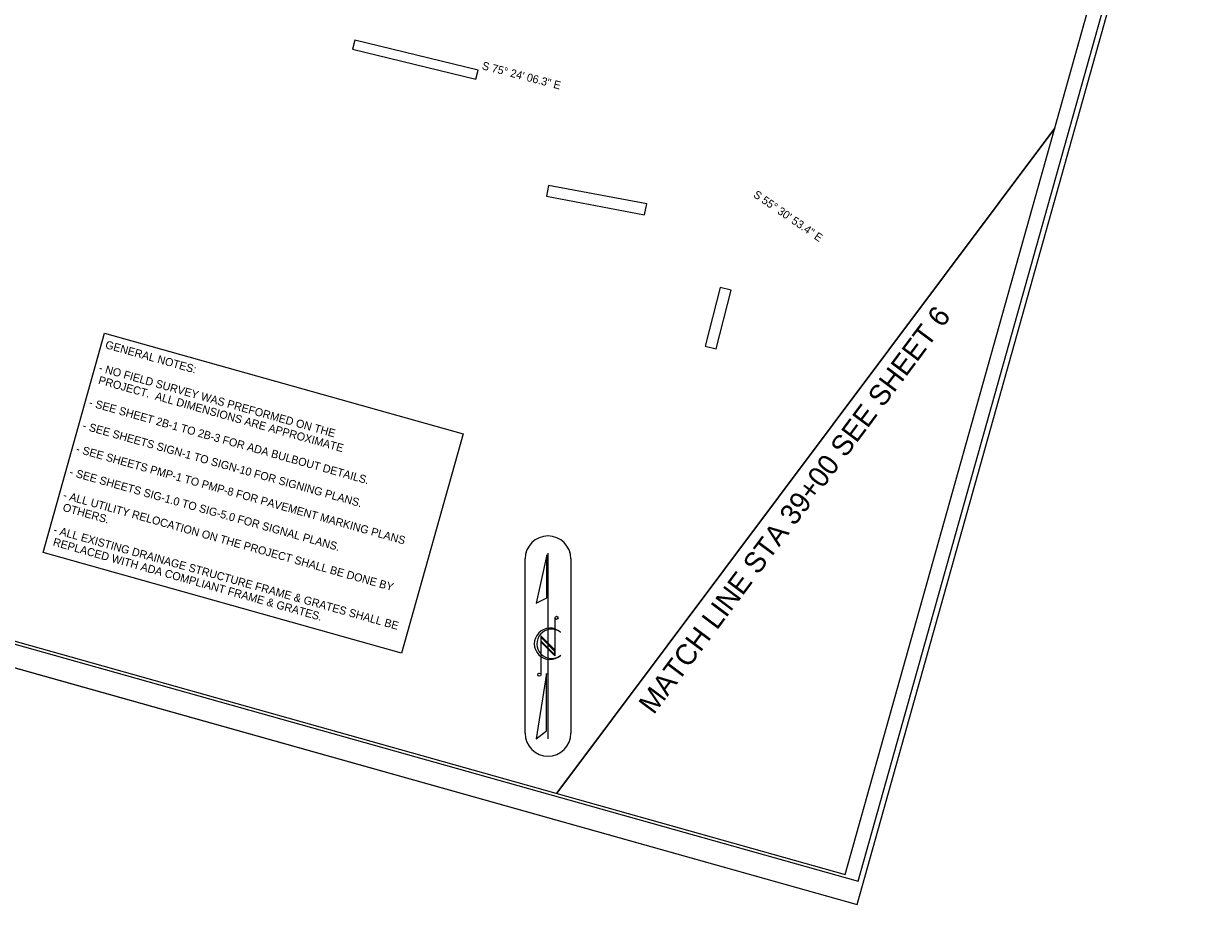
# Model space of a CAD drawing. Extents: x 928111 to 937215, y 684320 to 686530.
# Drawn here: x 929882 to 930907, y 684943 to 685714 of the extents above; entities that cross this region are included whole.
import ezdxf

# ---------------------------------------------------------------- set-up
doc = ezdxf.new("R2010")
doc.units = 0
for name, color, linetype in [('Exist Horizontal Alignment Direction Label', 7, 'Continuous'), ('Exist Horizontal Alignment Station Label', 7, 'Continuous'), ('Matchline', 7, 'Continuous'), ('Matchline Text', 7, 'Continuous'), ('Prop DSN Text', 7, 'Continuous'), ('Sheet Cutting Line CELL', 7, 'Continuous'), ('Sheet Layout Plan Border', 7, 'Continuous'), ('Sheet Plan CELL', 7, 'Continuous'), ('Sheet Plan Layout CELL', 7, 'Continuous'), ('Sheet Plot Border Inside CELL', 7, 'Continuous'), ('Sheet Plot Border Outside CELL', 7, 'Continuous')]:
    doc.layers.add(name, color=color, linetype=linetype)

msp = doc.modelspace()

# ---------------------------------------------------------------- linework, layer by layer
at = {"layer": 'Exist Horizontal Alignment Station Label'}
for p, q in [((930321, 685093.1), (930321, 685245.6)), ((930361, 685245.6), (930361, 685093.1))]:
    msp.add_line(p, q, dxfattribs=at)
for centre, start, end in [((930341, 685245.6), 90, 180), ((930341, 685245.6), 0, 90), ((930341, 685093.1), 180, 270), ((930341, 685093.1), 270, 0)]:
    msp.add_arc(centre, 20, start, end, dxfattribs=at)
at = {"layer": 'Matchline'}
msp.add_line((930784.2, 685621.9), (930348.6, 685040.6), dxfattribs=at)
at = {"layer": 'Prop DSN Text'}
for points in [[(930170.1, 685691.2), (930278, 685664.9), (930279.9, 685672.7), (930172, 685698.9)], [(930339.7, 685562.5), (930425.5, 685546.4), (930427.3, 685555.9), (930341.5, 685572)], [(930491.7, 685482.8), (930478.4, 685431.6), (930488, 685429.1), (930501.3, 685480.3)], [(929953.2, 685442.8), (930266.7, 685354.7), (930212.9, 685163.2), (929899.4, 685251.2)]]:
    msp.add_lwpolyline(points, close=True, dxfattribs=at)
at = {"layer": 'Sheet Cutting Line CELL'}
msp.add_line((928990.5, 685398.6), (930611.3, 684943.4), dxfattribs=at)
at = {"layer": 'Sheet Layout Plan Border'}
for p, q in [((930348.6, 685040.6), (930784.2, 685621.9)), ((930666.4, 685464.7), (930663.4, 685460.7))]:
    msp.add_line(p, q, dxfattribs=at)
at = {"layer": 'Sheet Plan CELL'}
for p, q in [((930341, 685088.1), (930341, 685250.6)), ((930347.1, 685194), (930347.1, 685160.7)), ((930347.1, 685165.9), (930334.7, 685178.3)), ((930334.7, 685178.3), (930334.7, 685144.4)), ((930351.7, 685181.6), (930351.9, 685181.5)), ((930347.1, 685164.6), (930334.7, 685177.1)), ((930334.7, 685177.1), (930334.7, 685174)), ((930347.1, 685161.6), (930334.7, 685174)), ((930334.7, 685174), (930347.1, 685161.6)), ((930347.1, 685160.7), (930334.7, 685173.1)), ((930347.1, 685161.6), (930347.1, 685164.6))]:
    msp.add_line(p, q, dxfattribs=at)
for points in [[(930884.9, 685980.5), (929440.8, 686386.2), (929156.9, 685375.3), (930601, 684969.7)], [(930339.9, 685249.1), (930330.6, 685206.9), (930339.9, 685211.6)], [(930339.7, 685145.3), (930330.5, 685088.1), (930339.7, 685095.3)]]:
    msp.add_lwpolyline(points, close=True, dxfattribs=at)
for centre in [(930348.5, 685194), (930333.4, 685144.3)]:
    msp.add_circle(centre, 1.32, dxfattribs=at)
for centre, radius, start, end in [((930342.7, 685171.3), 13.7, 47.84, 312.3941), ((930344.1, 685171.3), 12.8, 53.095, 308.6287)]:
    msp.add_arc(centre, radius, start, end, dxfattribs=at)
at = {"layer": 'Sheet Plan Layout CELL'}
msp.add_lwpolyline([(929440.8, 686386.2), (929156.9, 685375.3), (930601, 684969.7), (930827.7, 685776.9), (930597.4, 685841.6), (930654.6, 686045.2)], close=True, dxfattribs=at)
at = {"layer": 'Sheet Plot Border Inside CELL'}
msp.add_lwpolyline([(929008.4, 685414.4), (930612.3, 684963.9), (930897.6, 685979.6), (929293.7, 686430.1)], close=True, dxfattribs=at)
at = {"layer": 'Sheet Plot Border Outside CELL'}
msp.add_lwpolyline([(928990.5, 685398.6), (930611.3, 684943.4), (930907.4, 685997.6), (929286.6, 686452.8)], close=True, dxfattribs=at)

# ---------------------------------------------------------------- texts
at = {"layer": 'Exist Horizontal Alignment Direction Label'}
for s, rotation, p in [('S 75%%d 24\' 06.3" E', 345.4017, (930282.7, 685673.6)), ('S 55%%d 30\' 53.4" E', 325.5148, (930519.9, 685562.4))]:
    msp.add_text(s, height=7, rotation=rotation, dxfattribs=at).set_placement(p)
at = {"layer": 'Matchline Text'}
msp.add_text('MATCH LINE STA 39+00 SEE SHEET 6 ', height=18, rotation=53.2502, dxfattribs=at).set_placement((930433.4, 685108.7))
at = {"layer": 'Prop DSN Text'}
for s, p in [('GENERAL NOTES:', (929953.2, 685429.8)), ('- NO FIELD SURVEY WAS PREFORMED ON THE ', (929947.6, 685409.6)), (' PROJECT.  ALL DIMENSIONS ARE APPROXIMATE', (929944.7, 685399.5)), ('- SEE SHEET 2B-1 TO 2B-3 FOR ADA BULBOUT DETAILS.', (929939, 685379.3)), ('- SEE SHEETS SIGN-1 TO SIGN-10 FOR SIGNING PLANS.', (929933.4, 685359.1)), ('- SEE SHEETS PMP-1 TO PMP-8 FOR PAVEMENT MARKING PLANS  ', (929927.7, 685338.8)), ('- SEE SHEETS SIG-1.0 TO SIG-5.0 FOR SIGNAL PLANS.', (929922, 685318.6)), ('- ALL UTILITY RELOCATION ON THE PROJECT SHALL BE DONE BY ', (929916.3, 685298.4)), (' OTHERS.', (929913.5, 685288.3)), ('- ALL EXISTING DRAINAGE STRUCTURE FRAME & GRATES SHALL BE ', (929907.8, 685268.1)), (' REPLACED WITH ADA COMPLIANT FRAME & GRATES.', (929905, 685258))]:
    msp.add_text(s, height=7, rotation=344.3105, dxfattribs=at).set_placement(p)

doc.saveas('drawing.dxf')
